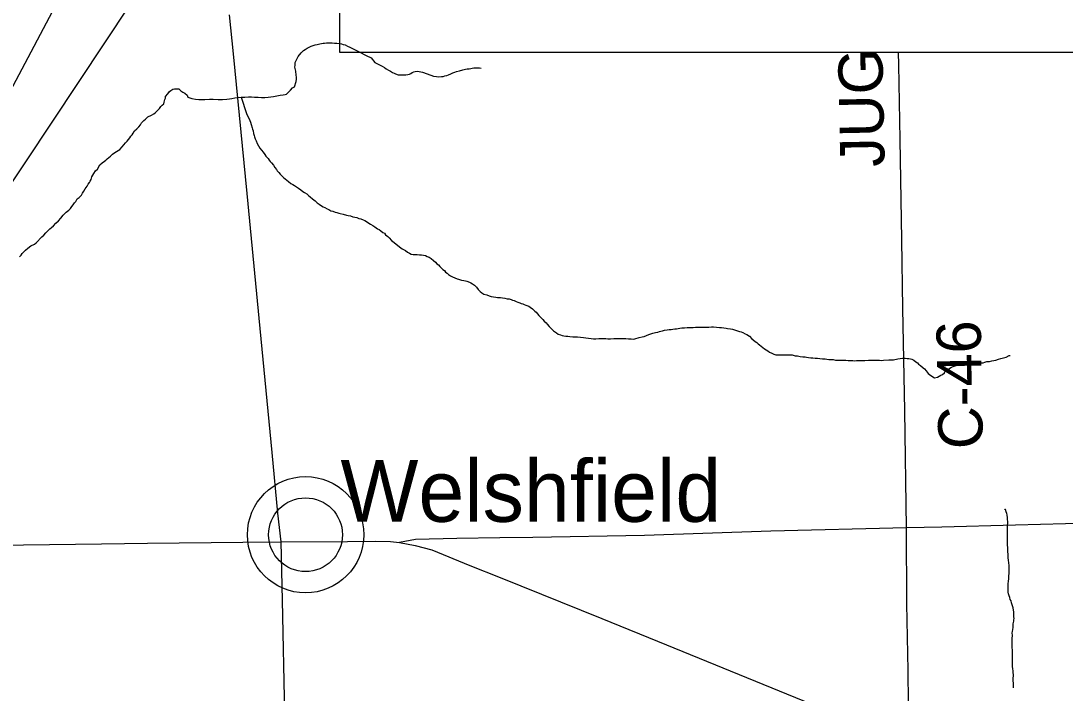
# Model space of a CAD drawing. Extents: x 0 to 34, y 0 to 22.
# Drawn here: x 6.59 to 7.926, y 16.836 to 17.696 of the extents above; entities that cross this region are included whole.
import ezdxf

# ---------------------------------------------------------------- set-up
doc = ezdxf.new("R2010")
doc.units = 0
for name, color, linetype in [('GM_X_County_Road', 7, 'Continuous'), ('GM_X_County_Road_Text', 7, 'Continuous'), ('GM_X_Minor_River', 7, 'Continuous'), ('GM_X_State_Route', 7, 'Continuous'), ('GM_X_Township_Road', 7, 'Continuous'), ('GM_X_Unincorporated', 7, 'Continuous'), ('GM_X_Unincorporated_Text', 7, 'Continuous'), ('GM_X_US_Route', 7, 'Continuous'), ('SH_Border', 7, 'Continuous')]:
    doc.layers.add(name, color=color, linetype=linetype)

msp = doc.modelspace()

# ---------------------------------------------------------------- linework, layer by layer
at = {"layer": 'GM_X_County_Road'}
for points in [[(7.7227, 17.0471), (7.7207, 17.1972), (7.7182, 17.3276), (7.717, 17.4155), (7.7145, 17.5439), (7.7128, 17.6394), (7.7126, 17.6552)], [(7.7257, 16.7715), (7.7252, 16.79), (7.7252, 16.8225), (7.7249, 16.8645), (7.723, 16.9497), (7.7227, 17.0471)]]:
    msp.add_lwpolyline(points, dxfattribs=at)
at = {"layer": 'GM_X_Minor_River'}
for points in [[(6.9017, 17.5976), (6.9059, 17.598), (6.9093, 17.5985), (6.9127, 17.5989), (6.9214, 17.6006), (6.9252, 17.6011), (6.9279, 17.6012), (6.9297, 17.6016), (6.9312, 17.6035), (6.9346, 17.607), (6.9372, 17.6097), (6.9398, 17.6113), (6.942, 17.6178), (6.9423, 17.6212), (6.9422, 17.6235), (6.9418, 17.6262), (6.9413, 17.6311), (6.9404, 17.6364), (6.9407, 17.6387), (6.9407, 17.6425), (6.9443, 17.6498), (6.9484, 17.6548), (6.9514, 17.6575), (6.9536, 17.6591), (6.9559, 17.6607), (6.9585, 17.6619), (6.9612, 17.6631), (6.9638, 17.6639), (6.9664, 17.6647), (6.9687, 17.6655), (6.9721, 17.6663), (6.9744, 17.6668), (6.9763, 17.6672), (6.9782, 17.6672), (6.9808, 17.6673), (6.9839, 17.6674), (6.9881, 17.6675), (6.9911, 17.6671), (6.9938, 17.6672), (6.9999, 17.6662), (7.0022, 17.6655), (7.0045, 17.6648), (7.0076, 17.6633), (7.0106, 17.6619), (7.0141, 17.6604), (7.0183, 17.6582), (7.0218, 17.6564), (7.0252, 17.6546), (7.0291, 17.6524), (7.0333, 17.6506), (7.036, 17.6491), (7.0379, 17.6484), (7.0426, 17.6424), (7.0484, 17.6395), (7.0518, 17.6377), (7.0549, 17.6358), (7.0572, 17.6344), (7.0599, 17.6325), (7.0626, 17.6311), (7.065, 17.6296), (7.0673, 17.6285), (7.0692, 17.6278), (7.0726, 17.6267), (7.0761, 17.6264), (7.0795, 17.6265), (7.0821, 17.6265), (7.0848, 17.627), (7.0867, 17.6274), (7.0886, 17.6282), (7.0904, 17.6294), (7.0923, 17.6302), (7.0942, 17.631), (7.0973, 17.6311), (7.0992, 17.6307), (7.1015, 17.6304), (7.1037, 17.6301), (7.1141, 17.6261), (7.1175, 17.625), (7.1214, 17.6244), (7.1244, 17.624), (7.1278, 17.6245), (7.1301, 17.6245), (7.132, 17.6253), (7.1346, 17.6258), (7.1369, 17.6266), (7.1396, 17.6278), (7.1422, 17.629), (7.1448, 17.6298), (7.1471, 17.6306), (7.1509, 17.6318), (7.155, 17.6331), (7.1584, 17.6339), (7.1607, 17.6343), (7.1634, 17.6344), (7.1653, 17.6348), (7.1672, 17.6352), (7.1691, 17.6353), (7.1713, 17.6353), (7.174, 17.6354), (7.1763, 17.6354), (7.1786, 17.6351)], [(6.6313, 17.4332), (6.6346, 17.4367), (6.638, 17.4398), (6.641, 17.4433), (6.6439, 17.4468), (6.6477, 17.4507), (6.651, 17.4534), (6.6532, 17.4557), (6.6547, 17.458), (6.6566, 17.4604), (6.6584, 17.4627), (6.6599, 17.4646), (6.6617, 17.4677), (6.6644, 17.4697), (6.6673, 17.4728), (6.6684, 17.4751), (6.6703, 17.4778), (6.6721, 17.4805), (6.6747, 17.4839), (6.6758, 17.4866), (6.6773, 17.4886), (6.6784, 17.4905), (6.6795, 17.4928), (6.6805, 17.4959), (6.6816, 17.4982), (6.6831, 17.5005), (6.6853, 17.5036), (6.6879, 17.5059), (6.6905, 17.5113), (6.6939, 17.514), (6.6965, 17.516), (6.6983, 17.5175), (6.7002, 17.5191), (6.7021, 17.5206), (6.7043, 17.5226), (6.7069, 17.5249), (6.7099, 17.5273), (6.7163, 17.5308), (6.7193, 17.5343), (6.7215, 17.537), (6.7237, 17.5394), (6.7256, 17.5417), (6.7275, 17.5436), (6.7293, 17.5459), (6.7304, 17.5479), (6.7319, 17.5498), (6.7334, 17.5517), (6.7352, 17.5548), (6.7382, 17.5575), (6.7404, 17.5602), (6.7427, 17.5626), (6.7441, 17.5653), (6.7471, 17.568), (6.7493, 17.5699), (6.7523, 17.573), (6.7568, 17.575), (6.7599, 17.5766), (6.7617, 17.5778), (6.7647, 17.5813), (6.7669, 17.5836), (6.7688, 17.5859), (6.7706, 17.5879), (6.7725, 17.5894), (6.7732, 17.5917), (6.7739, 17.5948), (6.7746, 17.5967), (6.7746, 17.599), (6.7776, 17.6021), (6.7798, 17.6052), (6.7817, 17.6064), (6.7843, 17.6083), (6.7862, 17.6087), (6.7896, 17.6088), (6.7919, 17.6085), (6.7942, 17.6062), (6.7969, 17.6044), (6.7996, 17.6029), (6.8023, 17.6007), (6.8031, 17.5981), (6.8085, 17.5963), (6.8131, 17.5953), (6.8173, 17.595), (6.8211, 17.595), (6.8249, 17.5951), (6.831, 17.5953), (6.8359, 17.5954), (6.842, 17.5951), (6.8477, 17.5949), (6.853, 17.5954), (6.8564, 17.5958), (6.8595, 17.5963), (6.8633, 17.5971), (6.8674, 17.5976), (6.8716, 17.598), (6.8762, 17.5981), (6.8811, 17.5982), (6.8849, 17.5983), (6.8887, 17.598), (6.8933, 17.5978), (6.8975, 17.5975), (6.9017, 17.5976)], [(6.8716, 17.598), (6.8782, 17.5769), (6.8825, 17.5679), (6.8833, 17.566), (6.8842, 17.563), (6.8854, 17.5588), (6.8862, 17.5569), (6.887, 17.555), (6.8874, 17.5516), (6.8883, 17.549), (6.8887, 17.5471), (6.8895, 17.5448), (6.8907, 17.5422), (6.8919, 17.5388), (6.8935, 17.5358), (6.8954, 17.5328), (6.8974, 17.5302), (6.8997, 17.5276), (6.9017, 17.5246), (6.9033, 17.5223), (6.906, 17.5194), (6.9072, 17.5175), (6.9087, 17.5156), (6.9103, 17.5138), (6.9127, 17.5108), (6.9146, 17.5081), (6.9166, 17.5055), (6.9178, 17.5037), (6.9197, 17.5014), (6.9213, 17.4995), (6.9232, 17.4977), (6.9259, 17.4951), (6.9321, 17.4899), (6.9352, 17.4877), (6.9375, 17.4862), (6.9398, 17.4851), (6.9422, 17.4833), (6.9449, 17.4814), (6.9479, 17.4792), (6.9503, 17.4774), (6.9526, 17.4759), (6.9557, 17.4741), (6.958, 17.4718), (6.9599, 17.4704), (6.963, 17.4678), (6.9661, 17.4652), (6.9688, 17.4626), (6.9712, 17.4611), (6.9742, 17.4589), (6.9765, 17.4578), (6.9785, 17.4567), (6.9816, 17.4549), (6.9835, 17.4542), (6.9862, 17.4527), (6.9888, 17.452), (6.9919, 17.4509), (6.9938, 17.4506), (6.9965, 17.4495), (6.9984, 17.4492), (7.0019, 17.4481), (7.0061, 17.447), (7.0084, 17.4467), (7.0114, 17.446), (7.0145, 17.4449), (7.0171, 17.4446), (7.0194, 17.4439), (7.0221, 17.4428), (7.0248, 17.4425), (7.0275, 17.441), (7.0298, 17.44), (7.0317, 17.4389), (7.0348, 17.4366), (7.0371, 17.4356), (7.0398, 17.4337), (7.0425, 17.4319), (7.046, 17.4297), (7.0483, 17.4286), (7.0502, 17.4271), (7.0529, 17.4249), (7.0549, 17.4238), (7.0561, 17.4219), (7.0591, 17.4197), (7.0607, 17.4178), (7.0638, 17.4148), (7.0673, 17.4119), (7.0743, 17.4063), (7.0774, 17.4041), (7.0793, 17.403), (7.0816, 17.4016), (7.0843, 17.3997), (7.087, 17.3982), (7.0889, 17.3972), (7.0916, 17.3968), (7.0946, 17.3965), (7.0969, 17.3966), (7.0996, 17.3962), (7.1022, 17.3963), (7.1049, 17.396), (7.1072, 17.3956), (7.1095, 17.3942), (7.1122, 17.3931)], [(6.588, 17.3939), (6.5899, 17.3958), (6.5913, 17.3981), (6.5936, 17.4001), (6.5954, 17.4024), (6.5984, 17.4048), (6.6025, 17.4079), (6.6071, 17.4099), (6.6093, 17.4118), (6.6167, 17.4192), (6.619, 17.4216), (6.6216, 17.4243), (6.6242, 17.427), (6.6268, 17.4297), (6.629, 17.4313), (6.6313, 17.4332)], [(7.1122, 17.3931), (7.1145, 17.3916), (7.1176, 17.389), (7.1203, 17.3868), (7.1219, 17.3849), (7.1238, 17.3835), (7.1258, 17.3812), (7.1277, 17.3794), (7.1297, 17.3775), (7.1316, 17.376), (7.1331, 17.3742), (7.1351, 17.3727), (7.137, 17.3712), (7.1393, 17.3694), (7.142, 17.3679), (7.1478, 17.3654), (7.1497, 17.365), (7.1535, 17.364), (7.1566, 17.3633), (7.1585, 17.3629), (7.1604, 17.3626), (7.1635, 17.3611), (7.1654, 17.3604), (7.1673, 17.3593), (7.17, 17.3575), (7.1727, 17.3549), (7.1747, 17.3519), (7.1774, 17.3493), (7.1794, 17.3478), (7.1821, 17.346), (7.1859, 17.3449), (7.189, 17.3438), (7.1916, 17.3431), (7.1943, 17.3424), (7.1974, 17.3421), (7.1993, 17.3418), (7.2012, 17.3418), (7.2035, 17.3415), (7.2061, 17.3412), (7.2088, 17.3408), (7.2119, 17.3401), (7.2145, 17.3398), (7.2168, 17.3391), (7.2187, 17.3384), (7.221, 17.3377), (7.2233, 17.3366), (7.2256, 17.3355), (7.2279, 17.3348), (7.2299, 17.3341), (7.2318, 17.3334), (7.2337, 17.3326), (7.2356, 17.3319), (7.2395, 17.3305), (7.2414, 17.3294), (7.2441, 17.3272), (7.2472, 17.3242), (7.2491, 17.3227), (7.2507, 17.3208), (7.2523, 17.3186), (7.2554, 17.3156), (7.2573, 17.3134), (7.2593, 17.3112), (7.2616, 17.3093), (7.2631, 17.3074), (7.2655, 17.3044), (7.2682, 17.3018), (7.2713, 17.2989), (7.2748, 17.2963), (7.2771, 17.2948), (7.2802, 17.2937), (7.2821, 17.293), (7.2844, 17.2927), (7.2871, 17.292), (7.2893, 17.292), (7.292, 17.2917), (7.2958, 17.2914), (7.3019, 17.2912), (7.3095, 17.2906), (7.3126, 17.2899), (7.316, 17.2896), (7.3194, 17.2893), (7.3225, 17.289), (7.3255, 17.289), (7.329, 17.2891), (7.3316, 17.2892), (7.3335, 17.2892), (7.3354, 17.2892), (7.3381, 17.2893), (7.3408, 17.289), (7.3442, 17.289), (7.3484, 17.2891), (7.3525, 17.2892), (7.3636, 17.2891), (7.367, 17.2888), (7.3704, 17.2889), (7.3731, 17.2885), (7.3754, 17.2886), (7.3807, 17.2906), (7.3845, 17.2914), (7.3871, 17.2919), (7.3931, 17.2943)], [(7.3931, 17.2943), (7.3981, 17.2959), (7.4018, 17.2968), (7.4045, 17.2972), (7.4068, 17.298), (7.4086, 17.2984), (7.4105, 17.2992), (7.4132, 17.2997), (7.4166, 17.3001), (7.4193, 17.3006), (7.4215, 17.3006), (7.4238, 17.301), (7.4265, 17.3015), (7.4287, 17.3015), (7.4306, 17.3019), (7.4329, 17.3024), (7.4352, 17.3028), (7.4386, 17.3029), (7.442, 17.3033), (7.4454, 17.3034), (7.45, 17.3035), (7.453, 17.3036), (7.4557, 17.3036), (7.458, 17.3037), (7.4603, 17.3037), (7.4622, 17.3038), (7.4648, 17.3038), (7.4671, 17.3039), (7.4698, 17.3039), (7.4732, 17.304), (7.4759, 17.3041), (7.4835, 17.3035), (7.4861, 17.3031), (7.4892, 17.3028), (7.4919, 17.3025), (7.4938, 17.3022), (7.4976, 17.3015), (7.5003, 17.3012), (7.5026, 17.3005), (7.5052, 17.2994), (7.5091, 17.2983), (7.5114, 17.2976), (7.5133, 17.2969), (7.5164, 17.2954), (7.5183, 17.2943), (7.5218, 17.2921), (7.5249, 17.2888), (7.5268, 17.2873), (7.5291, 17.2855), (7.5311, 17.284), (7.533, 17.2825), (7.5349, 17.281), (7.5369, 17.2792), (7.5388, 17.2777), (7.5411, 17.2762), (7.5431, 17.2747), (7.5454, 17.2733), (7.5473, 17.2718), (7.5504, 17.2703), (7.5531, 17.2693), (7.5557, 17.2685), (7.5584, 17.2682), (7.5641, 17.2683), (7.5672, 17.2684), (7.5691, 17.2685), (7.5732, 17.2682), (7.5763, 17.2682), (7.5805, 17.2672), (7.5832, 17.2669), (7.5866, 17.2662), (7.59, 17.2659), (7.5931, 17.2656), (7.595, 17.2652), (7.5973, 17.2649), (7.6003, 17.2646), (7.603, 17.2643), (7.6061, 17.2639), (7.6087, 17.264), (7.6121, 17.2637), (7.6152, 17.2634), (7.6186, 17.2631), (7.6209, 17.2627), (7.6236, 17.2624), (7.6262, 17.2625), (7.6289, 17.2622), (7.632, 17.2615), (7.6365, 17.2616), (7.6453, 17.2614), (7.6483, 17.2611), (7.6514, 17.2611), (7.654, 17.2612), (7.6563, 17.2608), (7.659, 17.2609), (7.6613, 17.261), (7.6643, 17.261), (7.6693, 17.2611), (7.6742, 17.2616), (7.6791, 17.2617), (7.6841, 17.2614), (7.6883, 17.2615), (7.6909, 17.2612)], [(7.6909, 17.2612), (7.6932, 17.2613), (7.7001, 17.2618), (7.7035, 17.2619), (7.7061, 17.2619), (7.7118, 17.2632), (7.7175, 17.2641), (7.7209, 17.2641), (7.7236, 17.2638), (7.7259, 17.2635), (7.7278, 17.2632), (7.7297, 17.2628), (7.732, 17.2617), (7.7347, 17.2595), (7.7367, 17.258), (7.7382, 17.2562), (7.7405, 17.2547), (7.744, 17.2517), (7.7459, 17.2502), (7.7479, 17.248), (7.7506, 17.2446), (7.7541, 17.2417), (7.7587, 17.2391), (7.7625, 17.2396), (7.7667, 17.2423), (7.7689, 17.2431), (7.7715, 17.2455), (7.7723, 17.2474), (7.7741, 17.2478), (7.7764, 17.2501), (7.7783, 17.2513), (7.7805, 17.2525), (7.7824, 17.2533), (7.785, 17.2541), (7.7881, 17.255), (7.79, 17.2554), (7.7922, 17.2558), (7.7953, 17.2563), (7.7991, 17.2563), (7.8032, 17.2568), (7.8067, 17.2569), (7.8109, 17.257), (7.8135, 17.2574), (7.8158, 17.2575), (7.8181, 17.2579), (7.8207, 17.2583), (7.823, 17.2588), (7.8256, 17.2596), (7.829, 17.26), (7.8321, 17.2605), (7.8347, 17.2609), (7.837, 17.2613), (7.8404, 17.2626), (7.8434, 17.2638), (7.8502, 17.2654), (7.854, 17.2674), (7.8555, 17.2674)], [(7.8596, 16.8422), (7.8596, 16.8434), (7.8595, 16.8457), (7.8595, 16.8483), (7.8594, 16.8514), (7.8593, 16.8548), (7.8597, 16.8575), (7.8596, 16.8594), (7.8592, 16.8613), (7.8591, 16.8639), (7.8587, 16.8666), (7.8586, 16.8696), (7.8585, 16.8745), (7.8585, 16.8783), (7.8584, 16.8818), (7.8583, 16.8856), (7.8582, 16.8901), (7.8581, 16.8943), (7.8581, 16.897), (7.858, 16.8992), (7.8579, 16.9049), (7.8582, 16.9095), (7.8581, 16.9122), (7.8584, 16.9148), (7.8588, 16.9167), (7.8591, 16.9198), (7.8594, 16.9217), (7.8594, 16.924), (7.8601, 16.9274), (7.86, 16.9293), (7.8604, 16.9312), (7.8603, 16.9331), (7.8603, 16.9361), (7.8602, 16.9396), (7.8598, 16.9418), (7.8593, 16.9445), (7.8585, 16.9471), (7.8573, 16.9509), (7.8565, 16.9535), (7.8553, 16.9554), (7.8549, 16.9577), (7.8541, 16.96), (7.8532, 16.9626), (7.8528, 16.9645), (7.8528, 16.9672), (7.8527, 16.9698), (7.8527, 16.9725), (7.853, 16.9755), (7.8533, 16.9789), (7.8536, 16.9816), (7.8539, 16.9835), (7.8539, 16.9858), (7.8542, 16.9885), (7.8541, 16.9923), (7.8541, 16.9953), (7.854, 16.9987), (7.8536, 17.0021), (7.8531, 17.0055), (7.853, 17.0086), (7.8529, 17.0135), (7.8525, 17.0165), (7.8524, 17.0196), (7.8519, 17.0268), (7.8518, 17.0287), (7.8518, 17.0321), (7.8521, 17.0352), (7.852, 17.0386), (7.852, 17.0412), (7.8519, 17.0454), (7.8521, 17.0504), (7.8525, 17.0527), (7.8524, 17.0549), (7.852, 17.0576), (7.8519, 17.0599), (7.8515, 17.0637), (7.8511, 17.0655), (7.8503, 17.0674), (7.8494, 17.0704), (7.8487, 17.0704), (7.8487, 17.0708)]]:
    msp.add_lwpolyline(points, dxfattribs=at)
at = {"layer": 'GM_X_State_Route'}
for points in [[(6.9225, 17.0291), (6.9185, 17.0659), (6.9111, 17.1434), (6.896, 17.3019), (6.8794, 17.4748), (6.8618, 17.6536), (6.8567, 17.7033)], [(6.9601, 14.3385), (6.9588, 14.4363), (6.9583, 14.5087), (6.9569, 14.6447), (6.9545, 14.8525), (6.9526, 15.0617), (6.9494, 15.2806), (6.9469, 15.4082), (6.945, 15.4974), (6.9426, 15.6618), (6.9415, 15.7144), (6.9391, 15.8578), (6.9382, 15.9358), (6.9378, 15.962), (6.9363, 16.1152), (6.9355, 16.1742), (6.9333, 16.3902), (6.932, 16.532), (6.9312, 16.5929), (6.9284, 16.739), (6.9273, 16.8086), (6.9244, 16.9544), (6.9225, 17.0291)]]:
    msp.add_lwpolyline(points, dxfattribs=at)
at = {"layer": 'GM_X_Township_Road'}
for points in [[(8.73, 17.0642), (8.6747, 17.0639), (8.6261, 17.0637), (8.4676, 17.0622), (8.3844, 17.0614), (8.3099, 17.0612), (8.1987, 17.0591), (8.0654, 17.0556), (7.926, 17.0523), (7.8621, 17.0506), (7.7682, 17.0478), (7.7227, 17.0471)], [(7.7227, 17.0471), (7.5491, 17.0426), (7.3876, 17.0373), (7.2447, 17.0345), (7.2023, 17.0341), (7.1474, 17.0333), (7.0945, 17.0321), (7.0742, 17.0282)]]:
    msp.add_lwpolyline(points, dxfattribs=at)
at = {"layer": 'GM_X_Unincorporated'}
for radius in [0.0744, 0.0472]:
    msp.add_circle((6.9539, 17.0382), radius, dxfattribs=at)
at = {"layer": 'GM_X_US_Route'}
for points in [[(6.3591, 17.0225), (6.3924, 17.0227), (6.6928, 17.0267), (6.7515, 17.0273)], [(6.7515, 17.0273), (6.8735, 17.0285), (6.9225, 17.0291)], [(6.9225, 17.0291), (7.0075, 17.0296), (7.0433, 17.0299), (7.0624, 17.0294), (7.0742, 17.0282), (7.094, 17.0245), (7.1153, 17.0189), (7.1643, 16.999), (7.2028, 16.9834), (7.3331, 16.9309), (7.4158, 16.8972), (7.6321, 16.8092), (7.7257, 16.7715), (7.7905, 16.7451)]]:
    msp.add_lwpolyline(points, dxfattribs=at)
at = {"layer": 'SH_Border'}
for points in [[(6.9977, 18.4031), (6.2611, 17.0116), (6.9977, 18.1206)], [(6.9977, 18.4031), (8.9734, 18.4031), (8.9734, 17.6552), (6.9977, 17.6552)]]:
    msp.add_lwpolyline(points, close=True, dxfattribs=at)

# ---------------------------------------------------------------- texts
at = {"layer": 'GM_X_County_Road_Text'}
for s, rotation, p in [('JUG', 91.1241, (7.6949, 17.5091)), ('C-46', 91.0286, (7.8206, 17.1481))]:
    msp.add_text(s, height=0.05682, rotation=rotation, dxfattribs=at).set_placement(p)
at = {"layer": 'GM_X_Unincorporated_Text'}
msp.add_text('Welshfield', height=0.07898, rotation=0, dxfattribs=at).set_placement((6.9986, 17.0547))

doc.saveas('drawing.dxf')
